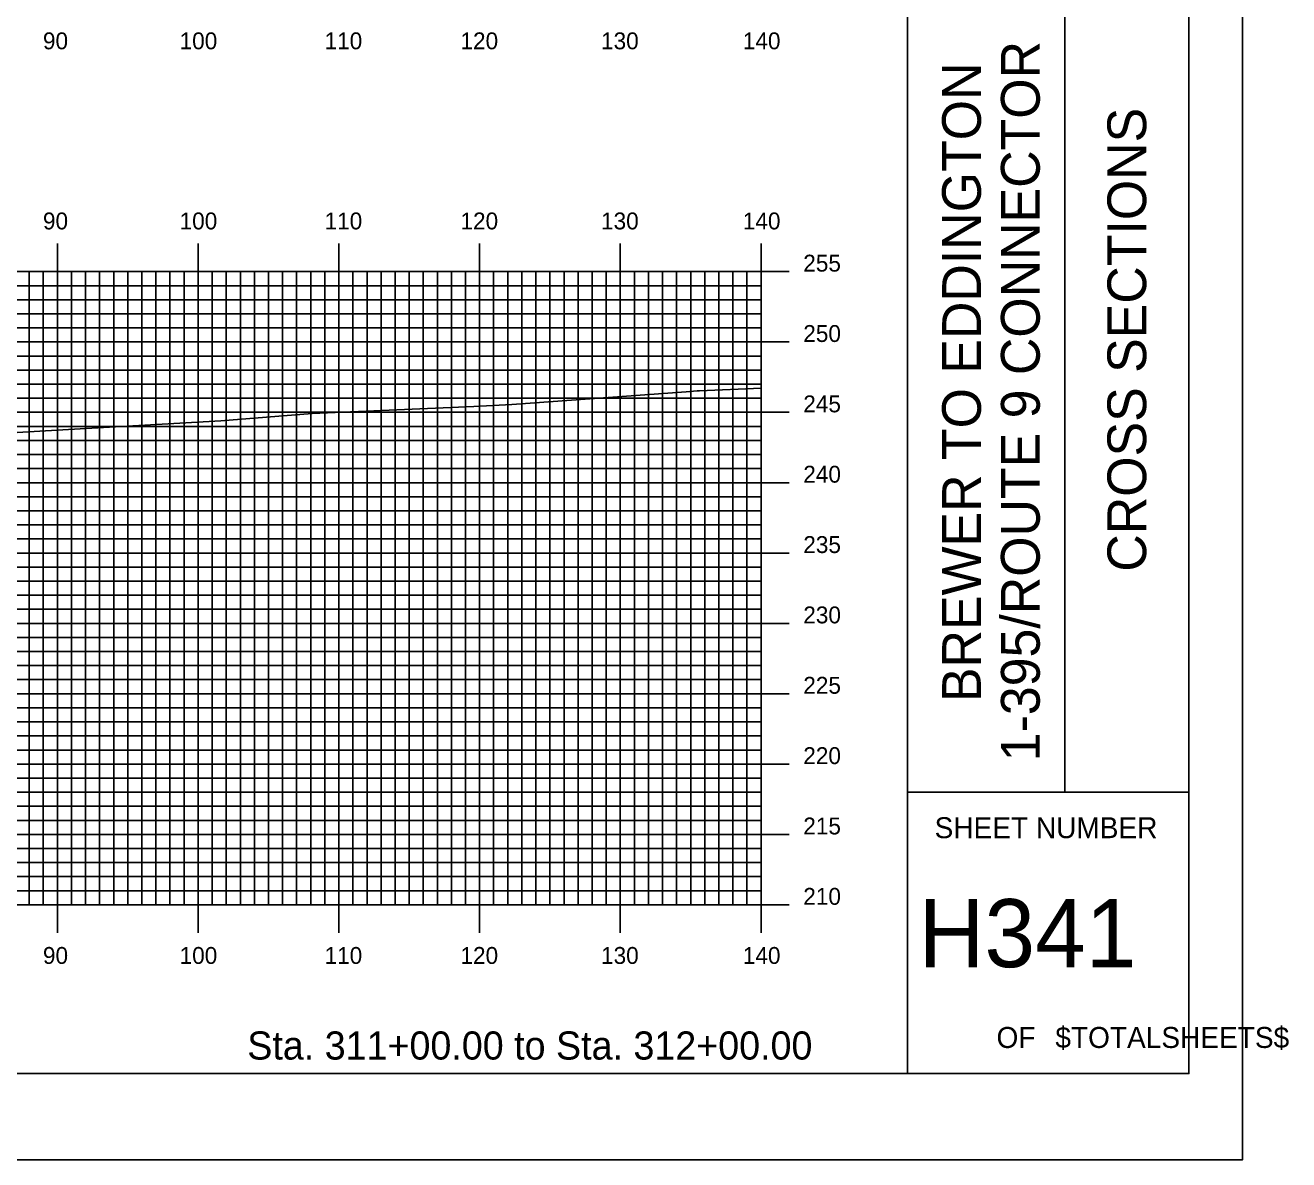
# Model space of a CAD drawing. Extents: x 1818457 to 1818800, y 442591 to 442811.
# Drawn here: x 1818710.4 to 1818800.1, y 442590.5 to 442671.2 of the extents above; entities that cross this region are included whole.
import ezdxf

# ---------------------------------------------------------------- set-up
doc = ezdxf.new("R2010")
doc.units = 0
for name, color, linetype in [('BORDER', 7, 'Continuous'), ('H_V ANNOTATION', 7, 'Continuous'), ('MAJOR', 7, 'Continuous'), ('MINOR', 7, 'Continuous'), ('PLOT BOUNDARY', 7, 'Continuous'), ('S_Roadway_Centerline', 7, 'Continuous')]:
    doc.layers.add(name, color=color, linetype=linetype)

msp = doc.modelspace()

# ---------------------------------------------------------------- linework, layer by layer
at = {"layer": 'BORDER'}
for p, q in [((1818773.038, 442596.665), (1818773.038, 442806.665)), ((1818784.22, 442616.671), (1818784.22, 442686.671)), ((1818773.038, 442616.671), (1818793.038, 442616.671))]:
    msp.add_line(p, q, dxfattribs=at)
msp.add_lwpolyline([(1818473.038, 442596.665), (1818793.038, 442596.665), (1818793.038, 442806.665), (1818473.038, 442806.665)], close=True, dxfattribs=at)
at = {"layer": 'MAJOR'}
for p, q in [((1818712.638, 442655.669), (1818712.638, 442653.665)), ((1818722.638, 442655.669), (1818722.638, 442653.665)), ((1818732.638, 442655.669), (1818732.638, 442653.665)), ((1818742.638, 442655.669), (1818742.638, 442653.665)), ((1818752.638, 442655.669), (1818752.638, 442653.665)), ((1818762.638, 442655.669), (1818762.638, 442653.665)), ((1818482.638, 442653.665), (1818762.638, 442653.665)), ((1818482.638, 442653.665), (1818762.638, 442653.665)), ((1818712.638, 442608.665), (1818712.638, 442653.665)), ((1818722.638, 442608.665), (1818722.638, 442653.665)), ((1818732.638, 442608.665), (1818732.638, 442653.665)), ((1818742.638, 442608.665), (1818742.638, 442653.665)), ((1818752.638, 442608.665), (1818752.638, 442653.665)), ((1818764.642, 442653.665), (1818760.634, 442653.665)), ((1818762.638, 442608.665), (1818762.638, 442653.665)), ((1818762.638, 442608.665), (1818762.638, 442653.665)), ((1818482.638, 442648.665), (1818762.638, 442648.665)), ((1818764.642, 442648.665), (1818760.634, 442648.665)), ((1818482.638, 442643.665), (1818762.638, 442643.665)), ((1818764.642, 442643.665), (1818760.634, 442643.665)), ((1818482.638, 442638.665), (1818762.638, 442638.665)), ((1818764.642, 442638.665), (1818760.634, 442638.665)), ((1818482.638, 442633.665), (1818762.638, 442633.665)), ((1818764.642, 442633.665), (1818760.634, 442633.665)), ((1818482.638, 442628.665), (1818762.638, 442628.665)), ((1818764.642, 442628.665), (1818760.634, 442628.665)), ((1818482.638, 442623.665), (1818762.638, 442623.665)), ((1818764.642, 442623.665), (1818760.634, 442623.665)), ((1818482.638, 442618.665), (1818762.638, 442618.665)), ((1818764.642, 442618.665), (1818760.634, 442618.665)), ((1818482.638, 442613.665), (1818762.638, 442613.665)), ((1818764.642, 442613.665), (1818760.634, 442613.665)), ((1818482.638, 442608.665), (1818762.638, 442608.665)), ((1818482.638, 442608.665), (1818762.638, 442608.665)), ((1818712.638, 442606.661), (1818712.638, 442608.665)), ((1818722.638, 442606.661), (1818722.638, 442608.665)), ((1818732.638, 442606.661), (1818732.638, 442608.665)), ((1818742.638, 442606.661), (1818742.638, 442608.665)), ((1818752.638, 442606.661), (1818752.638, 442608.665)), ((1818764.642, 442608.665), (1818760.634, 442608.665)), ((1818762.638, 442606.661), (1818762.638, 442608.665))]:
    msp.add_line(p, q, dxfattribs=at)
at = {"layer": 'MINOR'}
for p, q in [((1818710.638, 442608.665), (1818710.638, 442653.665)), ((1818711.638, 442608.665), (1818711.638, 442653.665)), ((1818713.638, 442608.665), (1818713.638, 442653.665)), ((1818714.638, 442608.665), (1818714.638, 442653.665)), ((1818715.638, 442608.665), (1818715.638, 442653.665)), ((1818716.638, 442608.665), (1818716.638, 442653.665)), ((1818717.638, 442608.665), (1818717.638, 442653.665)), ((1818718.638, 442608.665), (1818718.638, 442653.665)), ((1818719.638, 442608.665), (1818719.638, 442653.665)), ((1818720.638, 442608.665), (1818720.638, 442653.665)), ((1818721.638, 442608.665), (1818721.638, 442653.665)), ((1818723.638, 442608.665), (1818723.638, 442653.665)), ((1818724.638, 442608.665), (1818724.638, 442653.665)), ((1818725.638, 442608.665), (1818725.638, 442653.665)), ((1818726.638, 442608.665), (1818726.638, 442653.665)), ((1818727.638, 442608.665), (1818727.638, 442653.665)), ((1818728.638, 442608.665), (1818728.638, 442653.665)), ((1818729.638, 442608.665), (1818729.638, 442653.665)), ((1818730.638, 442608.665), (1818730.638, 442653.665)), ((1818731.638, 442608.665), (1818731.638, 442653.665)), ((1818733.638, 442608.665), (1818733.638, 442653.665)), ((1818734.638, 442608.665), (1818734.638, 442653.665)), ((1818735.638, 442608.665), (1818735.638, 442653.665)), ((1818736.638, 442608.665), (1818736.638, 442653.665)), ((1818737.638, 442608.665), (1818737.638, 442653.665)), ((1818738.638, 442608.665), (1818738.638, 442653.665)), ((1818739.638, 442608.665), (1818739.638, 442653.665)), ((1818740.638, 442608.665), (1818740.638, 442653.665)), ((1818741.638, 442608.665), (1818741.638, 442653.665)), ((1818743.638, 442608.665), (1818743.638, 442653.665)), ((1818744.638, 442608.665), (1818744.638, 442653.665)), ((1818745.638, 442608.665), (1818745.638, 442653.665)), ((1818746.638, 442608.665), (1818746.638, 442653.665)), ((1818747.638, 442608.665), (1818747.638, 442653.665)), ((1818748.638, 442608.665), (1818748.638, 442653.665)), ((1818749.638, 442608.665), (1818749.638, 442653.665)), ((1818750.638, 442608.665), (1818750.638, 442653.665)), ((1818751.638, 442608.665), (1818751.638, 442653.665)), ((1818753.638, 442608.665), (1818753.638, 442653.665)), ((1818754.638, 442608.665), (1818754.638, 442653.665)), ((1818755.638, 442608.665), (1818755.638, 442653.665)), ((1818756.638, 442608.665), (1818756.638, 442653.665)), ((1818757.638, 442608.665), (1818757.638, 442653.665)), ((1818758.638, 442608.665), (1818758.638, 442653.665)), ((1818759.638, 442608.665), (1818759.638, 442653.665)), ((1818760.638, 442608.665), (1818760.638, 442653.665)), ((1818761.638, 442608.665), (1818761.638, 442653.665)), ((1818482.638, 442652.665), (1818762.638, 442652.665)), ((1818762.638, 442652.665), (1818760.634, 442652.665)), ((1818482.638, 442651.665), (1818762.638, 442651.665)), ((1818762.638, 442651.665), (1818760.634, 442651.665)), ((1818482.638, 442650.665), (1818762.638, 442650.665)), ((1818762.638, 442650.665), (1818760.634, 442650.665)), ((1818482.638, 442649.665), (1818762.638, 442649.665)), ((1818762.638, 442649.665), (1818760.634, 442649.665)), ((1818482.638, 442647.665), (1818762.638, 442647.665)), ((1818762.638, 442647.665), (1818760.634, 442647.665)), ((1818482.638, 442646.665), (1818762.638, 442646.665)), ((1818762.638, 442646.665), (1818760.634, 442646.665)), ((1818482.638, 442645.665), (1818762.638, 442645.665)), ((1818762.638, 442645.665), (1818760.634, 442645.665)), ((1818482.638, 442644.665), (1818762.638, 442644.665)), ((1818762.638, 442644.665), (1818760.634, 442644.665)), ((1818482.638, 442642.665), (1818762.638, 442642.665)), ((1818762.638, 442642.665), (1818760.634, 442642.665)), ((1818482.638, 442641.665), (1818762.638, 442641.665)), ((1818762.638, 442641.665), (1818760.634, 442641.665)), ((1818482.638, 442640.665), (1818762.638, 442640.665)), ((1818762.638, 442640.665), (1818760.634, 442640.665)), ((1818482.638, 442639.665), (1818762.638, 442639.665)), ((1818762.638, 442639.665), (1818760.634, 442639.665)), ((1818482.638, 442637.665), (1818762.638, 442637.665)), ((1818762.638, 442637.665), (1818760.634, 442637.665)), ((1818482.638, 442636.665), (1818762.638, 442636.665)), ((1818762.638, 442636.665), (1818760.634, 442636.665)), ((1818482.638, 442635.665), (1818762.638, 442635.665)), ((1818762.638, 442635.665), (1818760.634, 442635.665)), ((1818482.638, 442634.665), (1818762.638, 442634.665)), ((1818762.638, 442634.665), (1818760.634, 442634.665)), ((1818482.638, 442632.665), (1818762.638, 442632.665)), ((1818762.638, 442632.665), (1818760.634, 442632.665)), ((1818482.638, 442631.665), (1818762.638, 442631.665)), ((1818762.638, 442631.665), (1818760.634, 442631.665)), ((1818482.638, 442630.665), (1818762.638, 442630.665)), ((1818762.638, 442630.665), (1818760.634, 442630.665)), ((1818482.638, 442629.665), (1818762.638, 442629.665)), ((1818762.638, 442629.665), (1818760.634, 442629.665)), ((1818482.638, 442627.665), (1818762.638, 442627.665)), ((1818762.638, 442627.665), (1818760.634, 442627.665)), ((1818482.638, 442626.665), (1818762.638, 442626.665)), ((1818762.638, 442626.665), (1818760.634, 442626.665)), ((1818482.638, 442625.665), (1818762.638, 442625.665)), ((1818762.638, 442625.665), (1818760.634, 442625.665)), ((1818482.638, 442624.665), (1818762.638, 442624.665)), ((1818762.638, 442624.665), (1818760.634, 442624.665)), ((1818482.638, 442622.665), (1818762.638, 442622.665)), ((1818762.638, 442622.665), (1818760.634, 442622.665)), ((1818482.638, 442621.665), (1818762.638, 442621.665)), ((1818762.638, 442621.665), (1818760.634, 442621.665)), ((1818482.638, 442620.665), (1818762.638, 442620.665)), ((1818762.638, 442620.665), (1818760.634, 442620.665)), ((1818482.638, 442619.665), (1818762.638, 442619.665)), ((1818762.638, 442619.665), (1818760.634, 442619.665)), ((1818482.638, 442617.665), (1818762.638, 442617.665)), ((1818762.638, 442617.665), (1818760.634, 442617.665)), ((1818482.638, 442616.665), (1818762.638, 442616.665)), ((1818762.638, 442616.665), (1818760.634, 442616.665)), ((1818482.638, 442615.665), (1818762.638, 442615.665)), ((1818762.638, 442615.665), (1818760.634, 442615.665)), ((1818482.638, 442614.665), (1818762.638, 442614.665)), ((1818762.638, 442614.665), (1818760.634, 442614.665)), ((1818482.638, 442612.665), (1818762.638, 442612.665)), ((1818762.638, 442612.665), (1818760.634, 442612.665)), ((1818482.638, 442611.665), (1818762.638, 442611.665)), ((1818762.638, 442611.665), (1818760.634, 442611.665)), ((1818482.638, 442610.665), (1818762.638, 442610.665)), ((1818762.638, 442610.665), (1818760.634, 442610.665)), ((1818482.638, 442609.665), (1818762.638, 442609.665)), ((1818762.638, 442609.665), (1818760.634, 442609.665))]:
    msp.add_line(p, q, dxfattribs=at)
at = {"layer": 'PLOT BOUNDARY'}
msp.add_lwpolyline([(1818456.852, 442590.547), (1818796.852, 442590.547), (1818796.852, 442810.547), (1818456.852, 442810.547)], close=True, dxfattribs=at)
at = {"layer": 'S_Roadway_Centerline'}
msp.add_lwpolyline([(1818707.322, 442642.095), (1818713.429, 442642.451), (1818724.261, 442643.058), (1818730.734, 442643.577), (1818742.23, 442644.079), (1818744.918, 442644.223), (1818757.318, 442645.126), (1818758.103, 442645.185), (1818758.272, 442645.189), (1818762.638, 442645.388)], dxfattribs=at)

# ---------------------------------------------------------------- texts
at = {"layer": 'BORDER'}
for s, p in [('1-395/ROUTE 9 CONNECTOR', (1818782.442, 442618.865)), ('BREWER TO EDDINGTON', (1818778.262, 442623.074)), ('CROSS SECTIONS', (1818790.007, 442632.339))]:
    msp.add_text(s, height=2.75575, rotation=90, dxfattribs=at).set_placement(p)
for s, height, p in [('SHEET NUMBER', 1.49054, (1818774.969, 442613.398)), ('H341', 4.8388, (1818773.84, 442604.23)), ('$TOTALSHEETS$', 1.49054, (1818783.551, 442598.491)), ('OF', 1.4905, (1818779.372, 442598.491))]:
    msp.add_text(s, height=height, dxfattribs=at).set_placement(p)
at = {"layer": 'H_V ANNOTATION'}
for s, height, p in [('90', 1.2, (1818711.611, 442669.465)), ('100', 1.2, (1818721.322, 442669.465)), ('110', 1.2, (1818731.622, 442669.465)), ('120', 1.2, (1818741.279, 442669.465)), ('130', 1.2, (1818751.268, 442669.465)), ('140', 1.2, (1818761.343, 442669.465)), ('90', 1.2, (1818711.611, 442656.665)), ('100', 1.2, (1818721.322, 442656.665)), ('110', 1.2, (1818731.622, 442656.665)), ('120', 1.2, (1818741.279, 442656.665)), ('130', 1.2, (1818751.268, 442656.665)), ('140', 1.2, (1818761.343, 442656.665)), ('255', 1.2, (1818765.638, 442653.665)), ('250', 1.2, (1818765.638, 442648.665)), ('245', 1.2, (1818765.638, 442643.665)), ('240', 1.2, (1818765.638, 442638.665)), ('235', 1.2, (1818765.638, 442633.665)), ('230', 1.2, (1818765.638, 442628.665)), ('225', 1.2, (1818765.638, 442623.665)), ('220', 1.2, (1818765.638, 442618.665)), ('215', 1.2, (1818765.638, 442613.665)), ('210', 1.2, (1818765.638, 442608.665)), ('90', 1.2, (1818711.611, 442604.465)), ('100', 1.2, (1818721.322, 442604.465)), ('110', 1.2, (1818731.622, 442604.465)), ('120', 1.2, (1818741.279, 442604.465)), ('130', 1.2, (1818751.268, 442604.465)), ('140', 1.2, (1818761.343, 442604.465)), ('Sta. 311+00.00 to Sta. 312+00.00', 2.0004, (1818726.13, 442597.665))]:
    msp.add_text(s, height=height, dxfattribs=at).set_placement(p)

doc.saveas('drawing.dxf')
